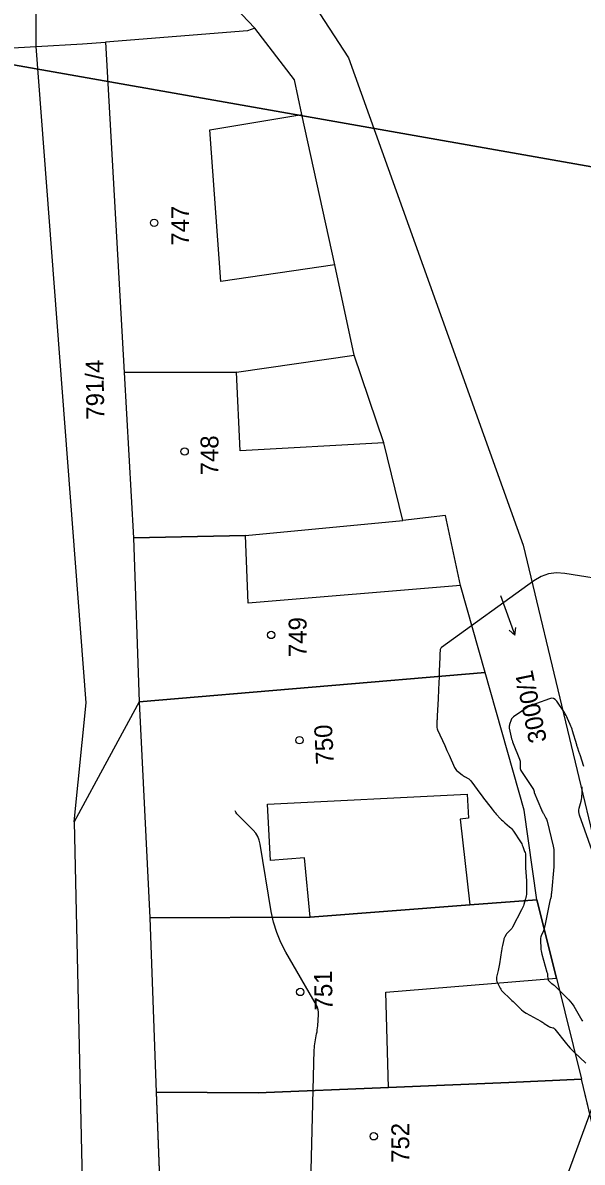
# Model space of a CAD drawing. Extents: x -534481 to -534256, y -1190577 to -1190138.
# Drawn here: x -534439 to -534412.4, y -1190397.5 to -1190343.4 of the extents above; entities that cross this region are included whole.
import ezdxf

# ---------------------------------------------------------------- set-up
doc = ezdxf.new("R2010")
doc.units = 0
for name, color, linetype in [('30', 7, 'Continuous'), ('31', 7, 'Continuous'), ('_N_text', 7, 'Continuous'), ('_rámeček', 7, 'Continuous'), ('Hranice parcel', 7, 'Continuous'), ('Parcelní čísla', 7, 'Continuous'), ('Polygon budovy', 7, 'Continuous'), ('Značky budov', 7, 'Continuous'), ('Značky kultur', 7, 'Continuous')]:
    doc.layers.add(name, color=color, linetype=linetype)

msp = doc.modelspace()

# ---------------------------------------------------------------- linework, layer by layer
at = {"layer": '30'}
for points in [[(-534412.325, -1190378.688), (-534412.5, -1190378.142), (-534412.514, -1190378.102), (-534412.527, -1190378.061), (-534412.54, -1190378.021), (-534412.554, -1190377.981), (-534412.61, -1190377.819), (-534412.623, -1190377.779), (-534412.637, -1190377.739), (-534412.649, -1190377.698), (-534412.662, -1190377.657), (-534412.861, -1190376.996), (-534412.885, -1190376.921), (-534412.911, -1190376.846), (-534412.94, -1190376.772), (-534412.971, -1190376.699), (-534413.098, -1190376.409), (-534413.132, -1190376.337), (-534413.168, -1190376.267), (-534413.208, -1190376.198), (-534413.25, -1190376.131), (-534413.614, -1190375.583), (-534413.684, -1190375.503), (-534413.765, -1190375.458), (-534413.858, -1190375.447), (-534413.962, -1190375.471), (-534414.569, -1190375.701), (-534414.594, -1190375.71), (-534414.619, -1190375.718), (-534414.645, -1190375.725), (-534414.67, -1190375.73), (-534414.774, -1190375.751), (-534414.799, -1190375.758), (-534414.824, -1190375.767), (-534414.847, -1190375.778), (-534414.87, -1190375.791), (-534415.668, -1190376.333), (-534415.703, -1190376.361), (-534415.732, -1190376.393), (-534415.755, -1190376.429), (-534415.772, -1190376.47), (-534415.85, -1190376.7), (-534415.855, -1190376.714), (-534415.859, -1190376.728), (-534415.862, -1190376.742), (-534415.865, -1190376.757), (-534415.874, -1190376.815), (-534415.875, -1190376.83), (-534415.876, -1190376.844), (-534415.874, -1190376.859), (-534415.872, -1190376.873), (-534415.777, -1190377.298), (-534415.758, -1190377.373), (-534415.737, -1190377.447), (-534415.712, -1190377.52), (-534415.685, -1190377.592), (-534415.378, -1190378.348), (-534415.362, -1190378.395), (-534415.35, -1190378.443), (-534415.343, -1190378.492), (-534415.342, -1190378.542), (-534415.345, -1190378.744), (-534415.342, -1190378.793), (-534415.332, -1190378.84), (-534415.315, -1190378.886), (-534415.291, -1190378.929), (-534414.723, -1190379.792), (-534414.717, -1190379.802), (-534414.712, -1190379.812), (-534414.707, -1190379.823), (-534414.704, -1190379.834), (-534414.691, -1190379.88), (-534414.688, -1190379.891), (-534414.684, -1190379.903), (-534414.68, -1190379.914), (-534414.676, -1190379.925), (-534414.336, -1190380.75), (-534414.316, -1190380.797), (-534414.294, -1190380.843), (-534414.271, -1190380.888), (-534414.247, -1190380.933), (-534414.147, -1190381.11), (-534414.124, -1190381.155), (-534414.103, -1190381.201), (-534414.086, -1190381.248), (-534414.073, -1190381.297), (-534413.782, -1190382.479), (-534413.765, -1190382.558), (-534413.753, -1190382.638), (-534413.746, -1190382.719), (-534413.743, -1190382.8), (-534413.743, -1190383.127), (-534413.744, -1190383.209), (-534413.747, -1190383.29), (-534413.751, -1190383.371), (-534413.757, -1190383.453), (-534413.865, -1190384.689), (-534413.866, -1190384.704), (-534413.867, -1190384.72), (-534413.868, -1190384.735), (-534413.868, -1190384.751), (-534413.868, -1190384.813), (-534413.869, -1190384.829), (-534413.871, -1190384.844), (-534413.874, -1190384.859), (-534413.878, -1190384.874), (-534413.911, -1190384.981), (-534413.918, -1190385.004), (-534413.924, -1190385.027), (-534413.93, -1190385.05), (-534413.934, -1190385.073), (-534414.175, -1190386.267), (-534414.188, -1190386.327), (-534414.205, -1190386.387), (-534414.225, -1190386.445), (-534414.248, -1190386.503), (-534414.345, -1190386.731), (-534414.366, -1190386.788), (-534414.38, -1190386.847), (-534414.386, -1190386.907), (-534414.386, -1190386.968), (-534414.366, -1190387.304), (-534414.359, -1190387.381), (-534414.348, -1190387.456), (-534414.333, -1190387.531), (-534414.314, -1190387.605), (-534414.074, -1190388.46), (-534414.064, -1190388.498), (-534414.056, -1190388.535), (-534414.05, -1190388.574), (-534414.046, -1190388.612), (-534414.029, -1190388.795), (-534414.024, -1190388.819), (-534414.016, -1190388.841), (-534414.004, -1190388.861), (-534413.989, -1190388.879), (-534413.912, -1190388.955), (-534413.897, -1190388.969), (-534413.881, -1190388.982), (-534413.865, -1190388.995), (-534413.848, -1190389.006), (-534413.778, -1190389.051), (-534413.761, -1190389.063), (-534413.745, -1190389.075), (-534413.729, -1190389.089), (-534413.714, -1190389.103), (-534413.042, -1190389.786), (-534412.957, -1190389.879), (-534412.878, -1190389.976), (-534412.805, -1190390.079), (-534412.739, -1190390.186), (-534412.416, -1190390.749), (-534412.387, -1190390.796)], [(-534411.841, -1190382.924), (-534412.526, -1190381.007), (-534412.549, -1190380.926), (-534412.559, -1190380.843), (-534412.556, -1190380.76), (-534412.541, -1190380.677), (-534412.455, -1190380.34), (-534412.437, -1190380.257), (-534412.422, -1190380.173), (-534412.412, -1190380.089), (-534412.407, -1190380.004), (-534412.396, -1190379.656)]]:
    msp.add_lwpolyline(points, dxfattribs=at)
at = {"layer": '31'}
for points in [[(-534410.832, -1190369.9), (-534413.227, -1190369.521), (-534413.622, -1190369.495), (-534413.999, -1190369.545), (-534414.358, -1190369.67), (-534414.699, -1190369.872), (-534419.086, -1190373.037), (-534419.116, -1190373.063), (-534419.138, -1190373.094), (-534419.152, -1190373.13), (-534419.157, -1190373.17), (-534419.163, -1190373.337), (-534419.165, -1190373.379), (-534419.166, -1190373.421), (-534419.168, -1190373.463), (-534419.169, -1190373.505), (-534419.194, -1190374.165), (-534419.197, -1190374.233), (-534419.2, -1190374.301), (-534419.202, -1190374.369), (-534419.204, -1190374.437), (-534419.214, -1190374.719), (-534419.217, -1190374.782), (-534419.219, -1190374.844), (-534419.222, -1190374.907), (-534419.225, -1190374.97), (-534419.237, -1190375.22), (-534419.24, -1190375.282), (-534419.243, -1190375.345), (-534419.246, -1190375.407), (-534419.249, -1190375.47), (-534419.292, -1190376.288), (-534419.295, -1190376.344), (-534419.298, -1190376.399), (-534419.3, -1190376.455), (-534419.303, -1190376.511), (-534419.314, -1190376.733), (-534419.313, -1190376.788), (-534419.306, -1190376.842), (-534419.293, -1190376.895), (-534419.273, -1190376.946), (-534418.932, -1190377.702), (-534418.829, -1190377.93), (-534418.726, -1190378.159), (-534418.466, -1190378.735), (-534418.438, -1190378.788), (-534418.405, -1190378.836), (-534418.367, -1190378.879), (-534418.322, -1190378.919), (-534418.106, -1190379.089), (-534418.073, -1190379.114), (-534418.038, -1190379.138), (-534418.002, -1190379.161), (-534417.966, -1190379.182), (-534417.817, -1190379.262), (-534417.782, -1190379.284), (-534417.749, -1190379.31), (-534417.72, -1190379.338), (-534417.693, -1190379.371), (-534417.211, -1190380.025), (-534417.15, -1190380.107), (-534417.088, -1190380.19), (-534417.027, -1190380.272), (-534416.965, -1190380.354), (-534416.683, -1190380.725), (-534416.637, -1190380.784), (-534416.589, -1190380.842), (-534416.54, -1190380.899), (-534416.489, -1190380.954), (-534416.278, -1190381.178), (-534416.229, -1190381.229), (-534416.178, -1190381.279), (-534416.125, -1190381.327), (-534416.071, -1190381.373), (-534415.852, -1190381.555), (-534415.8, -1190381.602), (-534415.751, -1190381.653), (-534415.706, -1190381.707), (-534415.665, -1190381.765), (-534415.338, -1190382.264), (-534415.305, -1190382.318), (-534415.275, -1190382.373), (-534415.248, -1190382.43), (-534415.225, -1190382.489), (-534415.136, -1190382.726), (-534415.117, -1190382.786), (-534415.103, -1190382.847), (-534415.095, -1190382.908), (-534415.093, -1190382.971), (-534415.095, -1190383.33), (-534415.095, -1190383.411), (-534415.093, -1190383.491), (-534415.089, -1190383.572), (-534415.084, -1190383.653), (-534415.059, -1190383.984), (-534415.054, -1190384.066), (-534415.05, -1190384.148), (-534415.048, -1190384.231), (-534415.048, -1190384.313), (-534415.05, -1190384.706), (-534415.053, -1190384.775), (-534415.061, -1190384.843), (-534415.074, -1190384.91), (-534415.092, -1190384.977), (-534415.174, -1190385.241), (-534415.196, -1190385.306), (-534415.22, -1190385.37), (-534415.248, -1190385.434), (-534415.278, -1190385.496), (-534415.706, -1190386.323), (-534415.726, -1190386.357), (-534415.748, -1190386.39), (-534415.773, -1190386.42), (-534415.801, -1190386.449), (-534415.925, -1190386.566), (-534415.949, -1190386.59), (-534415.971, -1190386.616), (-534415.992, -1190386.643), (-534416.011, -1190386.671), (-534416.083, -1190386.787), (-534416.1, -1190386.816), (-534416.113, -1190386.847), (-534416.124, -1190386.878), (-534416.133, -1190386.911), (-534416.191, -1190387.198), (-534416.202, -1190387.257), (-534416.213, -1190387.316), (-534416.224, -1190387.375), (-534416.233, -1190387.435), (-534416.334, -1190388.072), (-534416.347, -1190388.15), (-534416.362, -1190388.228), (-534416.377, -1190388.305), (-534416.394, -1190388.382), (-534416.468, -1190388.708), (-534416.477, -1190388.775), (-534416.475, -1190388.841), (-534416.46, -1190388.906), (-534416.434, -1190388.969), (-534416.304, -1190389.217), (-534416.269, -1190389.277), (-534416.23, -1190389.334), (-534416.186, -1190389.387), (-534416.137, -1190389.436), (-534415.867, -1190389.688), (-534415.805, -1190389.747), (-534415.744, -1190389.805), (-534415.683, -1190389.864), (-534415.622, -1190389.924), (-534415.351, -1190390.192), (-534415.284, -1190390.254), (-534415.213, -1190390.312), (-534415.138, -1190390.364), (-534415.06, -1190390.411), (-534414.37, -1190390.797), (-534414.327, -1190390.821), (-534414.286, -1190390.846), (-534414.244, -1190390.872), (-534414.204, -1190390.899), (-534414.008, -1190391.031), (-534413.984, -1190391.046), (-534413.959, -1190391.058), (-534413.933, -1190391.069), (-534413.906, -1190391.077), (-534413.798, -1190391.106), (-534413.772, -1190391.116), (-534413.748, -1190391.128), (-534413.727, -1190391.145), (-534413.708, -1190391.165), (-534413.154, -1190391.863), (-534413.065, -1190391.97), (-534412.972, -1190392.074), (-534412.876, -1190392.175), (-534412.776, -1190392.272), (-534412.222, -1190392.79)], [(-534425.344, -1190400.439), (-534425.133, -1190392.149), (-534425.128, -1190392.053), (-534425.12, -1190391.957), (-534425.108, -1190391.862), (-534425.092, -1190391.767), (-534425.02, -1190391.389), (-534425.003, -1190391.294), (-534424.989, -1190391.199), (-534424.978, -1190391.104), (-534424.969, -1190391.008), (-534424.927, -1190390.481), (-534424.926, -1190390.363), (-534424.942, -1190390.249), (-534424.976, -1190390.139), (-534425.028, -1190390.033), (-534426.484, -1190387.518), (-534426.724, -1190387.056), (-534426.92, -1190386.578), (-534427.072, -1190386.085), (-534427.179, -1190385.575), (-534427.7, -1190382.387), (-534427.745, -1190382.199), (-534427.817, -1190382.025), (-534427.916, -1190381.865), (-534428.042, -1190381.719), (-534428.755, -1190381.007), (-534428.811, -1190380.941), (-534428.856, -1190380.869), (-534428.888, -1190380.792)]]:
    msp.add_lwpolyline(points, dxfattribs=at)
at = {"layer": '_N_text'}
msp.add_lwpolyline([(-534406.078, -1190512.511), (-534434.703, -1190456.89), (-534410.94, -1190392.232)], dxfattribs=at)
at = {"layer": '_rámeček'}
for points in [[(-534333.072, -1190257.49), (-534426.145, -1190241.079), (-534444.378, -1190344.484), (-534298.134, -1190370.27)], [(-534298.134, -1190370.27), (-534444.378, -1190344.484), (-534462.611, -1190447.888), (-534316.367, -1190473.675)]]:
    msp.add_lwpolyline(points, dxfattribs=at)
at = {"layer": 'Hranice parcel'}
for p, q in [((-534439.74, -1190344.56), (-534438.35, -1190344.48)), ((-534435.05, -1190344.28), (-534434.16, -1190359.98)), ((-534434.16, -1190359.98), (-534433.73, -1190367.83)), ((-534433.73, -1190367.83), (-534433.45, -1190375.62)), ((-534433.45, -1190375.62), (-534417.02, -1190374.22)), ((-534433.45, -1190375.62), (-534432.95, -1190385.88)), ((-534432.95, -1190385.88), (-534432.64, -1190394.16)), ((-534410.38, -1190402.1), (-534412.44, -1190393.55)), ((-534432.64, -1190394.16), (-534432.33, -1190402.39))]:
    msp.add_line(p, q, dxfattribs=at)
for points in [[(-534425.49, -1190303.95), (-534427.4, -1190310.23), (-534432.23, -1190329.13), (-534431.92, -1190332.1), (-534423.51, -1190345.02), (-534415.2, -1190368.18), (-534411.18, -1190384.97), (-534409.63, -1190387.68)], [(-534438.35, -1190344.48), (-534438.33, -1190339.63), (-534438.5, -1190324.13)], [(-534435.67, -1190327.29), (-534436.59, -1190334.53), (-534427.96, -1190343.61)], [(-534427.96, -1190343.61), (-534428.3, -1190343.74), (-534435.05, -1190344.28)], [(-534423.23, -1190359.15), (-534424.16, -1190354.86), (-534425.72, -1190347.72), (-534426.08, -1190346.07), (-534427.96, -1190343.61)], [(-534438.35, -1190344.48), (-534436.15, -1190344.36), (-534435.05, -1190344.28)], [(-534436.55, -1190381.32), (-534435.98, -1190375.67), (-534438.35, -1190344.48)], [(-534434.16, -1190359.98), (-534428.83, -1190359.95), (-534423.23, -1190359.15)], [(-534420.93, -1190367), (-534421.83, -1190363.31), (-534423.23, -1190359.15)], [(-534417.02, -1190374.22), (-534418.19, -1190370.1), (-534418.9, -1190366.76), (-534420.93, -1190367)], [(-534433.73, -1190367.83), (-534428.4, -1190367.72), (-534420.93, -1190367)], [(-534414.55, -1190385.03), (-534415.16, -1190380.76), (-534417.02, -1190374.22)], [(-534433.45, -1190375.62), (-534434.88, -1190378.25), (-534436.55, -1190381.32)], [(-534436.55, -1190381.32), (-534435.62, -1190422.59), (-534435.57, -1190424.53), (-534435.47, -1190429), (-534438.93, -1190449.34), (-534449.16, -1190465.21), (-534465.46, -1190480.21), (-534468.814, -1190483.101)], [(-534432.95, -1190385.88), (-534425.33, -1190385.85), (-534417.74, -1190385.27), (-534414.55, -1190385.03)], [(-534414.55, -1190385.03), (-534413.63, -1190388.75), (-534412.44, -1190393.55)], [(-534432.64, -1190394.16), (-534427.8, -1190394.2), (-534421.6, -1190393.94), (-534415.89, -1190393.7), (-534412.44, -1190393.55)]]:
    msp.add_lwpolyline(points, dxfattribs=at)
at = {"layer": 'Polygon budovy'}
for points in [[(-534435.05, -1190344.28), (-534434.16, -1190359.98), (-534428.83, -1190359.95), (-534423.23, -1190359.15), (-534424.16, -1190354.86), (-534429.58, -1190355.65), (-534430.09, -1190348.45), (-534425.72, -1190347.72), (-534426.08, -1190346.07), (-534427.96, -1190343.61), (-534428.3, -1190343.74)], [(-534434.16, -1190359.98), (-534433.73, -1190367.83), (-534428.4, -1190367.72), (-534420.93, -1190367), (-534421.83, -1190363.31), (-534428.65, -1190363.7), (-534428.83, -1190359.95)], [(-534433.73, -1190367.83), (-534433.45, -1190375.62), (-534417.02, -1190374.22), (-534418.19, -1190370.1), (-534428.28, -1190370.94), (-534428.4, -1190367.72)], [(-534433.45, -1190375.62), (-534432.95, -1190385.88), (-534425.33, -1190385.85), (-534425.59, -1190383.03), (-534427.22, -1190383.16), (-534427.35, -1190380.48), (-534417.86, -1190380.01), (-534417.8, -1190381.14), (-534418.2, -1190381.2), (-534417.74, -1190385.27), (-534414.55, -1190385.03), (-534415.16, -1190380.76), (-534417.02, -1190374.22)], [(-534432.95, -1190385.88), (-534432.64, -1190394.16), (-534427.8, -1190394.2), (-534421.6, -1190393.94), (-534421.73, -1190389.42), (-534413.63, -1190388.75), (-534414.55, -1190385.03), (-534417.74, -1190385.27), (-534425.33, -1190385.85)], [(-534432.64, -1190394.16), (-534432.33, -1190402.39), (-534427.61, -1190402.33), (-534427.86, -1190398.67), (-534414.87, -1190398.34), (-534413.97, -1190398.32), (-534413.47, -1190402.14), (-534410.38, -1190402.1), (-534412.44, -1190393.55), (-534415.89, -1190393.7), (-534421.6, -1190393.94), (-534427.8, -1190394.2)]]:
    msp.add_lwpolyline(points, close=True, dxfattribs=at)
at = {"layer": 'Značky budov'}
for centre in [(-534432.746, -1190352.861), (-534431.293, -1190363.724), (-534427.182, -1190372.443), (-534425.833, -1190377.446), (-534425.8, -1190389.404), (-534422.307, -1190396.261)]:
    msp.add_circle(centre, 0.175, dxfattribs=at)
at = {"layer": 'Značky kultur'}
for p, q in [((-534416.284, -1190370.57), (-534415.597, -1190372.459)), ((-534415.597, -1190372.459), (-534415.867, -1190372.208)), ((-534415.597, -1190372.459), (-534415.551, -1190372.093))]:
    msp.add_line(p, q, dxfattribs=at)

# ---------------------------------------------------------------- texts
at = {"layer": 'Parcelní čísla'}
for s, rotation, p in [('747', 90, (-534431.08, -1190353.948)), ('791/4', 91, (-534435.107, -1190362.204)), ('748', 90, (-534429.687, -1190364.859)), ('749', 90, (-534425.5, -1190373.493)), ('3000/1', 101.5337, (-534414.077, -1190377.479)), ('750', 93, (-534424.196, -1190378.574)), ('751', 91, (-534424.261, -1190390.273)), ('752', 90, (-534420.619, -1190397.524))]:
    msp.add_text(s, height=0.85, rotation=rotation, dxfattribs=at).set_placement(p)

doc.saveas('drawing.dxf')
